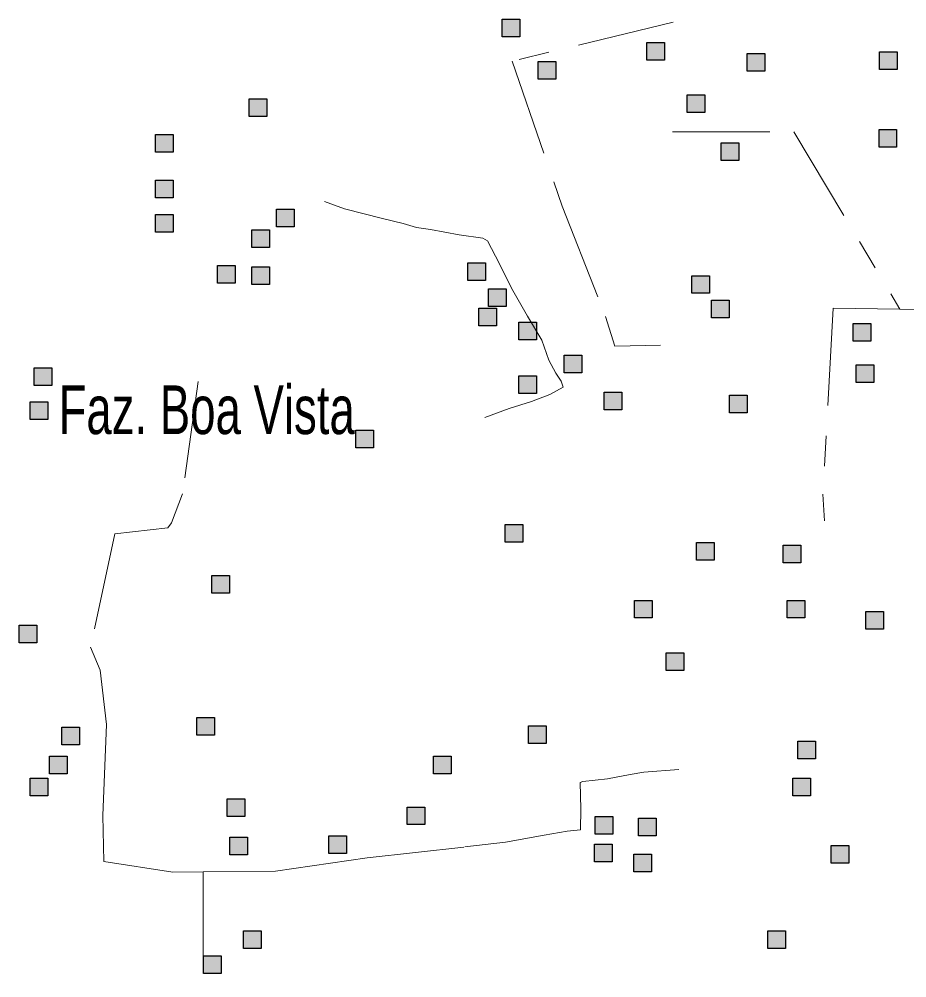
# Model space of a CAD drawing. Extents: x 445.4 to 500, y 8728.7 to 8784.
# Drawn here: x 476.078 to 478.996, y 8767.051 to 8770.201 of the extents above; entities that cross this region are included whole.
import ezdxf

# ---------------------------------------------------------------- set-up
doc = ezdxf.new("R2010")
doc.units = 0
doc.header["$LTSCALE"] = 0.064
doc.linetypes.add('DOT_DASHED', pattern=[7.7, 5, -1.2, 0.3, -1.2])
doc.layers.add('2', color=7, linetype='Continuous', lineweight=25)
doc.layers.add('22', color=7, linetype='DOT_DASHED', lineweight=13)
doc.layers.add('61', color=7, linetype='Continuous')

msp = doc.modelspace()

# ---------------------------------------------------------------- hatches: boundary and pattern name
at = {"layer": '2'}
for points in [[(477.6665, 8770.2013), (477.7245, 8770.2013), (477.7245, 8770.1433), (477.6665, 8770.1433)], [(478.1413, 8770.125), (478.1993, 8770.125), (478.1993, 8770.067), (478.1413, 8770.067)], [(478.472, 8770.0889), (478.53, 8770.0889), (478.53, 8770.0309), (478.472, 8770.0309)], [(478.9064, 8770.0935), (478.9644, 8770.0935), (478.9644, 8770.0355), (478.9064, 8770.0355)], [(477.7842, 8770.0618), (477.8422, 8770.0618), (477.8422, 8770.0038), (477.7842, 8770.0038)], [(478.2745, 8769.9531), (478.3325, 8769.9531), (478.3325, 8769.8951), (478.2745, 8769.8951)], [(476.834, 8769.9395), (476.892, 8769.9395), (476.892, 8769.8815), (476.834, 8769.8815)], [(478.905, 8769.8391), (478.963, 8769.8391), (478.963, 8769.7811), (478.905, 8769.7811)], [(476.5262, 8769.8218), (476.5842, 8769.8218), (476.5842, 8769.7638), (476.5262, 8769.7638)], [(478.386, 8769.7947), (478.444, 8769.7947), (478.444, 8769.7367), (478.386, 8769.7367)], [(476.5262, 8769.6724), (476.5842, 8769.6724), (476.5842, 8769.6144), (476.5262, 8769.6144)], [(476.9245, 8769.5773), (476.9825, 8769.5773), (476.9825, 8769.5193), (476.9245, 8769.5193)], [(476.5262, 8769.5592), (476.5842, 8769.5592), (476.5842, 8769.5012), (476.5262, 8769.5012)], [(476.843, 8769.5094), (476.901, 8769.5094), (476.901, 8769.4514), (476.843, 8769.4514)], [(476.7299, 8769.3917), (476.7879, 8769.3917), (476.7879, 8769.3337), (476.7299, 8769.3337)], [(476.843, 8769.3872), (476.901, 8769.3872), (476.901, 8769.3292), (476.843, 8769.3292)], [(477.5534, 8769.4008), (477.6114, 8769.4008), (477.6114, 8769.3428), (477.5534, 8769.3428)], [(478.2896, 8769.3584), (478.3476, 8769.3584), (478.3476, 8769.3004), (478.2896, 8769.3004)], [(477.6213, 8769.3147), (477.6793, 8769.3147), (477.6793, 8769.2567), (477.6213, 8769.2567)], [(478.3544, 8769.2776), (478.4124, 8769.2776), (478.4124, 8769.2196), (478.3544, 8769.2196)], [(477.5896, 8769.2514), (477.6476, 8769.2514), (477.6476, 8769.1934), (477.5896, 8769.1934)], [(477.7209, 8769.2061), (477.7789, 8769.2061), (477.7789, 8769.1481), (477.7209, 8769.1481)], [(478.8204, 8769.2016), (478.8784, 8769.2016), (478.8784, 8769.1436), (478.8204, 8769.1436)], [(477.8702, 8769.0974), (477.9282, 8769.0974), (477.9282, 8769.0394), (477.8702, 8769.0394)], [(476.1278, 8769.0557), (476.1858, 8769.0557), (476.1858, 8768.9977), (476.1278, 8768.9977)], [(478.8295, 8769.0657), (478.8875, 8769.0657), (478.8875, 8769.0077), (478.8295, 8769.0077)], [(477.7209, 8769.0295), (477.7789, 8769.0295), (477.7789, 8768.9715), (477.7209, 8768.9715)], [(478.0014, 8768.9752), (478.0594, 8768.9752), (478.0594, 8768.9172), (478.0014, 8768.9172)], [(476.1144, 8768.9435), (476.1724, 8768.9435), (476.1724, 8768.8855), (476.1144, 8768.8855)], [(478.4132, 8768.9661), (478.4712, 8768.9661), (478.4712, 8768.9081), (478.4132, 8768.9081)], [(477.1854, 8768.8505), (477.2434, 8768.8505), (477.2434, 8768.7925), (477.1854, 8768.7925)], [(477.6756, 8768.5406), (477.7336, 8768.5406), (477.7336, 8768.4826), (477.6756, 8768.4826)], [(478.3046, 8768.4817), (478.3626, 8768.4817), (478.3626, 8768.4237), (478.3046, 8768.4237)], [(478.5897, 8768.4726), (478.6477, 8768.4726), (478.6477, 8768.4146), (478.5897, 8768.4146)], [(476.7118, 8768.373), (476.7698, 8768.373), (476.7698, 8768.315), (476.7118, 8768.315)], [(478.101, 8768.2915), (478.159, 8768.2915), (478.159, 8768.2335), (478.101, 8768.2335)], [(478.6032, 8768.2915), (478.6612, 8768.2915), (478.6612, 8768.2335), (478.6032, 8768.2335)], [(478.8612, 8768.2553), (478.9192, 8768.2553), (478.9192, 8768.1973), (478.8612, 8768.1973)], [(476.0782, 8768.2101), (476.1362, 8768.2101), (476.1362, 8768.1521), (476.0782, 8768.1521)], [(478.205, 8768.1195), (478.263, 8768.1195), (478.263, 8768.0615), (478.205, 8768.0615)], [(476.662, 8767.9067), (476.72, 8767.9067), (476.72, 8767.8487), (476.662, 8767.8487)], [(476.2185, 8767.875), (476.2765, 8767.875), (476.2765, 8767.817), (476.2185, 8767.817)], [(477.7525, 8767.8795), (477.8105, 8767.8795), (477.8105, 8767.8215), (477.7525, 8767.8215)], [(478.638, 8767.8289), (478.696, 8767.8289), (478.696, 8767.7709), (478.638, 8767.7709)], [(476.1778, 8767.7799), (476.2358, 8767.7799), (476.2358, 8767.7219), (476.1778, 8767.7219)], [(477.4403, 8767.7799), (477.4983, 8767.7799), (477.4983, 8767.7219), (477.4403, 8767.7219)], [(476.1144, 8767.7075), (476.1724, 8767.7075), (476.1724, 8767.6495), (476.1144, 8767.6495)], [(478.6212, 8767.707), (478.6792, 8767.707), (478.6792, 8767.649), (478.6212, 8767.649)], [(476.7616, 8767.6396), (476.8196, 8767.6396), (476.8196, 8767.5816), (476.7616, 8767.5816)], [(477.3543, 8767.6124), (477.4123, 8767.6124), (477.4123, 8767.5544), (477.3543, 8767.5544)], [(477.9717, 8767.5807), (478.0297, 8767.5807), (478.0297, 8767.5227), (477.9717, 8767.5227)], [(478.1145, 8767.5762), (478.1725, 8767.5762), (478.1725, 8767.5182), (478.1145, 8767.5182)], [(476.7706, 8767.5128), (476.8286, 8767.5128), (476.8286, 8767.4548), (476.7706, 8767.4548)], [(477.0964, 8767.5174), (477.1544, 8767.5174), (477.1544, 8767.4594), (477.0964, 8767.4594)], [(477.9696, 8767.4902), (478.0276, 8767.4902), (478.0276, 8767.4322), (477.9696, 8767.4322)], [(478.748, 8767.4857), (478.806, 8767.4857), (478.806, 8767.4277), (478.748, 8767.4277)], [(478.0986, 8767.4569), (478.1566, 8767.4569), (478.1566, 8767.3989), (478.0986, 8767.3989)], [(476.8159, 8767.205), (476.8739, 8767.205), (476.8739, 8767.147), (476.8159, 8767.147)], [(478.5399, 8767.205), (478.5979, 8767.205), (478.5979, 8767.147), (478.5399, 8767.147)], [(476.6846, 8767.1235), (476.7426, 8767.1235), (476.7426, 8767.0655), (476.6846, 8767.0655)]]:
    msp.add_hatch(color=256, dxfattribs=at).paths.add_polyline_path(points)

# ---------------------------------------------------------------- linework, layer by layer
for points in [[(477.6665, 8770.2013), (477.7245, 8770.2013), (477.7245, 8770.1433), (477.6665, 8770.1433)], [(478.1413, 8770.125), (478.1993, 8770.125), (478.1993, 8770.067), (478.1413, 8770.067)], [(478.472, 8770.0889), (478.53, 8770.0889), (478.53, 8770.0309), (478.472, 8770.0309)], [(478.9064, 8770.0935), (478.9644, 8770.0935), (478.9644, 8770.0355), (478.9064, 8770.0355)], [(477.7842, 8770.0618), (477.8422, 8770.0618), (477.8422, 8770.0038), (477.7842, 8770.0038)], [(478.2745, 8769.9531), (478.3325, 8769.9531), (478.3325, 8769.8951), (478.2745, 8769.8951)], [(476.834, 8769.9395), (476.892, 8769.9395), (476.892, 8769.8815), (476.834, 8769.8815)], [(478.905, 8769.8391), (478.963, 8769.8391), (478.963, 8769.7811), (478.905, 8769.7811)], [(476.5262, 8769.8218), (476.5842, 8769.8218), (476.5842, 8769.7638), (476.5262, 8769.7638)], [(478.386, 8769.7947), (478.444, 8769.7947), (478.444, 8769.7367), (478.386, 8769.7367)], [(476.5262, 8769.6724), (476.5842, 8769.6724), (476.5842, 8769.6144), (476.5262, 8769.6144)], [(476.9245, 8769.5773), (476.9825, 8769.5773), (476.9825, 8769.5193), (476.9245, 8769.5193)], [(476.5262, 8769.5592), (476.5842, 8769.5592), (476.5842, 8769.5012), (476.5262, 8769.5012)], [(476.843, 8769.5094), (476.901, 8769.5094), (476.901, 8769.4514), (476.843, 8769.4514)], [(476.7299, 8769.3917), (476.7879, 8769.3917), (476.7879, 8769.3337), (476.7299, 8769.3337)], [(476.843, 8769.3872), (476.901, 8769.3872), (476.901, 8769.3292), (476.843, 8769.3292)], [(477.5534, 8769.4008), (477.6114, 8769.4008), (477.6114, 8769.3428), (477.5534, 8769.3428)], [(478.2896, 8769.3584), (478.3476, 8769.3584), (478.3476, 8769.3004), (478.2896, 8769.3004)], [(477.6213, 8769.3147), (477.6793, 8769.3147), (477.6793, 8769.2567), (477.6213, 8769.2567)], [(478.3544, 8769.2776), (478.4124, 8769.2776), (478.4124, 8769.2196), (478.3544, 8769.2196)], [(477.5896, 8769.2514), (477.6476, 8769.2514), (477.6476, 8769.1934), (477.5896, 8769.1934)], [(477.7209, 8769.2061), (477.7789, 8769.2061), (477.7789, 8769.1481), (477.7209, 8769.1481)], [(478.8204, 8769.2016), (478.8784, 8769.2016), (478.8784, 8769.1436), (478.8204, 8769.1436)], [(477.8702, 8769.0974), (477.9282, 8769.0974), (477.9282, 8769.0394), (477.8702, 8769.0394)], [(476.1278, 8769.0557), (476.1858, 8769.0557), (476.1858, 8768.9977), (476.1278, 8768.9977)], [(478.8295, 8769.0657), (478.8875, 8769.0657), (478.8875, 8769.0077), (478.8295, 8769.0077)], [(477.7209, 8769.0295), (477.7789, 8769.0295), (477.7789, 8768.9715), (477.7209, 8768.9715)], [(478.0014, 8768.9752), (478.0594, 8768.9752), (478.0594, 8768.9172), (478.0014, 8768.9172)], [(476.1144, 8768.9435), (476.1724, 8768.9435), (476.1724, 8768.8855), (476.1144, 8768.8855)], [(478.4132, 8768.9661), (478.4712, 8768.9661), (478.4712, 8768.9081), (478.4132, 8768.9081)], [(477.1854, 8768.8505), (477.2434, 8768.8505), (477.2434, 8768.7925), (477.1854, 8768.7925)], [(477.6756, 8768.5406), (477.7336, 8768.5406), (477.7336, 8768.4826), (477.6756, 8768.4826)], [(478.3046, 8768.4817), (478.3626, 8768.4817), (478.3626, 8768.4237), (478.3046, 8768.4237)], [(478.5897, 8768.4726), (478.6477, 8768.4726), (478.6477, 8768.4146), (478.5897, 8768.4146)], [(476.7118, 8768.373), (476.7698, 8768.373), (476.7698, 8768.315), (476.7118, 8768.315)], [(478.101, 8768.2915), (478.159, 8768.2915), (478.159, 8768.2335), (478.101, 8768.2335)], [(478.6032, 8768.2915), (478.6612, 8768.2915), (478.6612, 8768.2335), (478.6032, 8768.2335)], [(478.8612, 8768.2553), (478.9192, 8768.2553), (478.9192, 8768.1973), (478.8612, 8768.1973)], [(476.0782, 8768.2101), (476.1362, 8768.2101), (476.1362, 8768.1521), (476.0782, 8768.1521)], [(478.205, 8768.1195), (478.263, 8768.1195), (478.263, 8768.0615), (478.205, 8768.0615)], [(476.662, 8767.9067), (476.72, 8767.9067), (476.72, 8767.8487), (476.662, 8767.8487)], [(476.2185, 8767.875), (476.2765, 8767.875), (476.2765, 8767.817), (476.2185, 8767.817)], [(477.7525, 8767.8795), (477.8105, 8767.8795), (477.8105, 8767.8215), (477.7525, 8767.8215)], [(478.638, 8767.8289), (478.696, 8767.8289), (478.696, 8767.7709), (478.638, 8767.7709)], [(476.1778, 8767.7799), (476.2358, 8767.7799), (476.2358, 8767.7219), (476.1778, 8767.7219)], [(477.4403, 8767.7799), (477.4983, 8767.7799), (477.4983, 8767.7219), (477.4403, 8767.7219)], [(476.1144, 8767.7075), (476.1724, 8767.7075), (476.1724, 8767.6495), (476.1144, 8767.6495)], [(478.6212, 8767.707), (478.6792, 8767.707), (478.6792, 8767.649), (478.6212, 8767.649)], [(476.7616, 8767.6396), (476.8196, 8767.6396), (476.8196, 8767.5816), (476.7616, 8767.5816)], [(477.3543, 8767.6124), (477.4123, 8767.6124), (477.4123, 8767.5544), (477.3543, 8767.5544)], [(477.9717, 8767.5807), (478.0297, 8767.5807), (478.0297, 8767.5227), (477.9717, 8767.5227)], [(478.1145, 8767.5762), (478.1725, 8767.5762), (478.1725, 8767.5182), (478.1145, 8767.5182)], [(476.7706, 8767.5128), (476.8286, 8767.5128), (476.8286, 8767.4548), (476.7706, 8767.4548)], [(477.0964, 8767.5174), (477.1544, 8767.5174), (477.1544, 8767.4594), (477.0964, 8767.4594)], [(477.9696, 8767.4902), (478.0276, 8767.4902), (478.0276, 8767.4322), (477.9696, 8767.4322)], [(478.748, 8767.4857), (478.806, 8767.4857), (478.806, 8767.4277), (478.748, 8767.4277)], [(478.0986, 8767.4569), (478.1566, 8767.4569), (478.1566, 8767.3989), (478.0986, 8767.3989)], [(476.8159, 8767.205), (476.8739, 8767.205), (476.8739, 8767.147), (476.8159, 8767.147)], [(478.5399, 8767.205), (478.5979, 8767.205), (478.5979, 8767.147), (478.5399, 8767.147)], [(476.6846, 8767.1235), (476.7426, 8767.1235), (476.7426, 8767.0655), (476.6846, 8767.0655)]]:
    msp.add_lwpolyline(points, close=True, dxfattribs=at)
at = {"layer": '22'}
for points in [[(478.2278, 8770.1915), (477.6989, 8770.0636), (477.8636, 8769.5868), (478.0059, 8769.2247), (478.0362, 8769.1273), (478.1865, 8769.1297)], [(478.2262, 8769.8308), (478.625, 8769.8308), (478.9735, 8769.2485)], [(479.2653, 8769.622), (479.2642, 8769.2454), (478.9735, 8769.2487)], [(477.0825, 8769.6024), (477.1479, 8769.5776), (477.2728, 8769.5463), (477.3402, 8769.5299), (477.3845, 8769.5167), (477.4305, 8769.5102), (477.5242, 8769.4921), (477.603, 8769.4822), (477.6178, 8769.4724), (477.6441, 8769.423), (477.7016, 8769.3096), (477.7493, 8769.2258), (477.7969, 8769.1469), (477.8199, 8769.0811), (477.8429, 8769.0384), (477.8601, 8769.0115), (477.8662, 8768.9918), (477.8228, 8768.968), (477.7629, 8768.945), (477.6892, 8768.9224), (477.6092, 8768.8925)], [(478.9735, 8769.2487), (478.7545, 8769.2511), (478.7205, 8768.6402), (478.7263, 8768.5523)], [(476.6672, 8769.0106), (476.6149, 8768.6412), (476.5792, 8768.546), (476.5673, 8768.5302), (476.3926, 8768.5104), (476.3132, 8768.1377), (476.345, 8768.0624), (476.3648, 8767.884), (476.353, 8767.5841), (476.357, 8767.4334), (476.5832, 8767.3978), (476.683, 8767.3989)], [(477.6768, 8767.497), (477.8043, 8767.5196), (477.8801, 8767.5325), (477.9235, 8767.5372), (477.9244, 8767.6065), (477.9226, 8767.6925), (477.9318, 8767.6962), (478.0122, 8767.7045), (478.0869, 8767.7188), (478.1322, 8767.727), (478.2464, 8767.7361)], [(476.683, 8767.3989), (476.9206, 8767.4017), (477.2223, 8767.4453), (477.5438, 8767.481), (477.6768, 8767.497)], [(476.683, 8767.3989), (476.6831, 8766.9949), (476.9444, 8766.7893), (477.1661, 8766.6311), (477.4455, 8766.5275), (477.4434, 8766.5284)]]:
    msp.add_lwpolyline(points, dxfattribs=at)

# ---------------------------------------------------------------- texts
at = {"layer": '61', "width": 0.7}
msp.add_text('Faz. Boa Vista', height=0.16, dxfattribs=at).set_placement((476.2077, 8768.8379))

doc.saveas('drawing.dxf')
